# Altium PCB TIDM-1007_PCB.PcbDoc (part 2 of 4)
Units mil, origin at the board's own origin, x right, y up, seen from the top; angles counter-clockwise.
Board outline 9645.67 x 3346.46 mil, 6 copper layers (Top Layer, Signal Layer 1, Signal Layer 2, Signal Layer 3, Signal Layer 4, Bottom Layer), stack 60.2 mil thick; 189 components, 109 nets, 620 pads, 278 vias.
Unrouted connection lines stored in the file: 5.
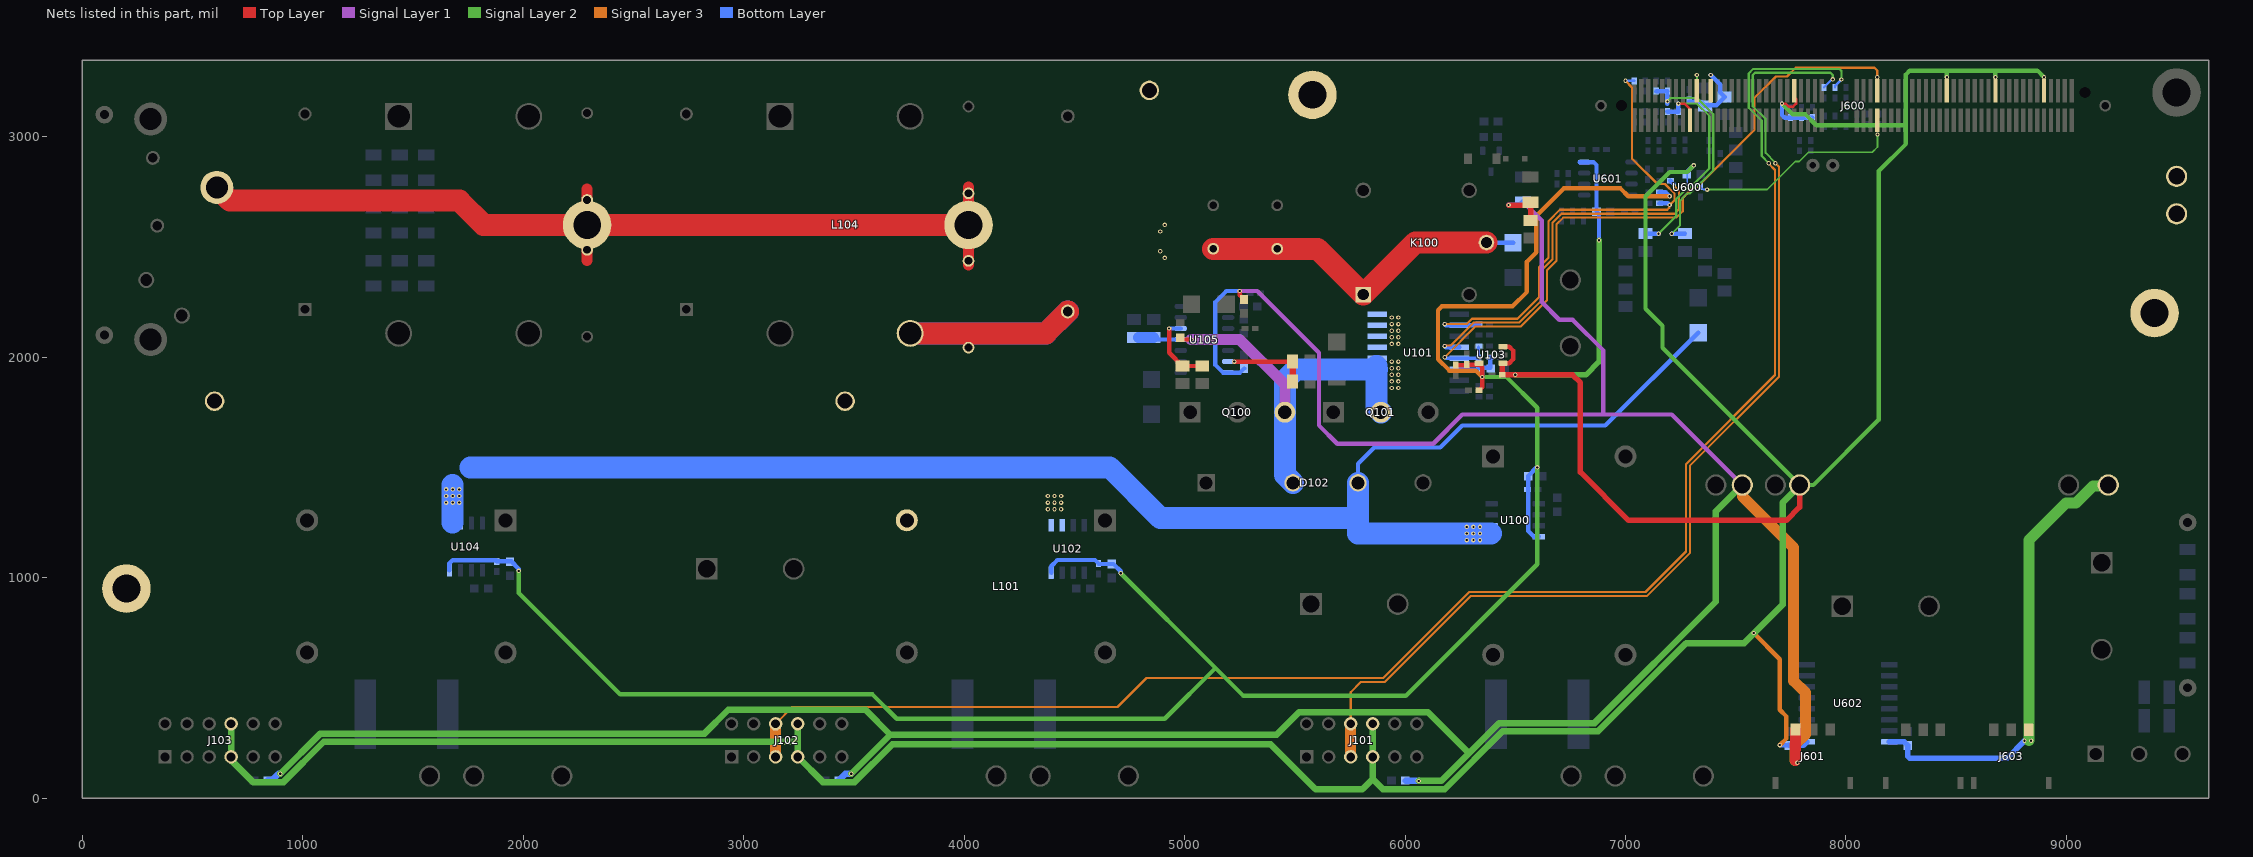
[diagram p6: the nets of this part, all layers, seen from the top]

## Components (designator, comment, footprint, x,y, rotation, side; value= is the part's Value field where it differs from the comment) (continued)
TP600 "Suggest using a net name here" Mill-Max_0312-0-15-15-34-27-10-0 6750,2350 r0 top
TP601 "Suggest using a net name here" Mill-Max_0312-0-15-15-34-27-10-0 9500,2820 r90 top
TP602 "Suggest using a net name here" Mill-Max_0312-0-15-15-34-27-10-0 6750,2050 r90 top
TP603 "Suggest using a net name here" Mill-Max_0312-0-15-15-34-27-10-0 9500,2650 r90 top
TP604 "Suggest using a net name here" Mill-Max_0312-0-15-15-34-27-10-0 7530,1420 r90 top
TP605 "Suggest using a net name here" Mill-Max_0312-0-15-15-34-27-10-0 9190,1420 r90 top
TP606 "Suggest using a net name here" Mill-Max_0312-0-15-15-34-27-10-0 7410,1420 r90 top
TP607 "Suggest using a net name here" Mill-Max_0312-0-15-15-34-27-10-0 9010,1420 r90 top
TP608 "Suggest using a net name here" Mill-Max_0312-0-15-15-34-27-10-0 7790,1420 r90 top
TP609 "Suggest using a net name here" Mill-Max_0312-0-15-15-34-27-10-0 7680,1420 r90 top
U100 "ACS722LLCTR-10AB-T" SOIC-8 6500,1260 r0 bottom
U101 "ACS716KLATR-12CB-NL-T" SOIC-16 6060,2020 r0 bottom
U102 "ACS722LLCTR-10AB-T" SOIC-8 4470,1130 r270 bottom
U103 "TLV71333PQDBVRQ1" DBV0005A_N 6390,2010 r180 top
U104 "ACS722LLCTR-10AB-T" SOIC-8 1740,1140.32 r270 bottom
U105 "UCC27714D" D0014A_N 5090,2080 r180 bottom
U600 "SN74LVC1G3157DRYR" DRY0006A 7280,2770 r90 bottom
U601 "OPA2376AIDG4" D0008A_N 6920,2810 r180 bottom
U602 "ISO7831DWR" DW0016B_N 8010,430 r0 bottom

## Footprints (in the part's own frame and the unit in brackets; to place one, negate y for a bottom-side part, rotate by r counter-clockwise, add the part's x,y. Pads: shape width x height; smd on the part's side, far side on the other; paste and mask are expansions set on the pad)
5S [mm] "TH, 4-Leads, Body 4.6x30mm"
  rect 2x2 hole 1.5: 1(-12.5,0)
  round 2 hole 1.5: 2(-2.5,0) 3(5,0) 4(12.5,0)
  silkscreen extent -15,-1.55 15,3.05, body extent -15,-1.55 15,3.05, height 24
0402 [mm] "0402 from SM-752 data"
  rect 0.8x0.6 smd: 1(-0.6,0) 2(0.6,0)
  silkscreen extent -1.22,-0.52 1.22,0.52, body extent -0.55,-0.3 0.55,0.3, height 0.6
0603 [mm] "0603 from SM-752 data"
  rect 1x0.95 smd: 1(-0.8,0) 2(0.8,0)
  silkscreen extent -1.52,-0.69 1.52,0.69, body extent -0.87,-0.47 0.87,0.47, height 1
0805_HV [mil] "0805 with 30mil clearance between pads"
  rect 50x63 smd: 1(-40,0) 2(40,0)
  silkscreen extent -74,-40 74,40, body extent -43,-29 43,29, height 57
1206 [mm] "1206 from SM-752 data"
  rect 1.3x1.85 smd: 1(-1.45,0) 2(1.45,0)
  silkscreen extent -2.4,-1.21 2.4,1.21, body extent -1.7,-0.9 1.7,0.9, height 1.35
1210_220 [mm] "1210"
  rect 1.3x2.7 smd: 1(-1.45,0) 2(1.45,0)
  silkscreen extent -2.32,-1.57 2.32,1.57, body extent -1.7,-1.35 1.7,1.35, height 2.2
B32923_15mm [mm] "Epcos film capacitors, 22.5mm spacing"
  rect 1.5x1.5 hole 1: 1(-11.25,0)
  round 1.5 hole 1: 2(11.25,0)
  silkscreen extent -13.25,-3 13.25,3, body extent -13.25,-3 13.25,3, height 15
B58031I_1084x785x450 [mm] "SMD, 2-Leads, Body 6.84x7.85mm"
  rect 2.5x8 smd: 1(-4.75,0) 2(4.75,0)
  silkscreen extent -3.2,-3.92 3.2,3.93, body extent -5.67,-4.17 5.67,4.18, height 4.5
controlCARD-120HSEC [mm] "Pads are not numbered according to Samtec datasheet."
  rect 0.5x2.724 smd: 1(-23.357,-1.678) 2(-23.357,1.722) 3(-22.557,-1.678) 4(-22.557,1.722) 5(-21.757,-1.678) 6(-21.757,1.722) 7(-20.957,-1.678) 8(-20.957,1.722) 9(-20.157,-1.678) 10(-20.157,1.722) 11(-19.357,-1.678) 12(-19.357,1.722) 13(-18.557,-1.678) 14(-18.557,1.722) 15(-17.757,-1.678) 16(-17.757,1.722) 17(-16.957,-1.678) 18(-16.957,1.722) 19(-16.157,-1.678) 20(-16.157,1.722) 21(-15.357,-1.678) 22(-15.357,1.722) 23(-14.557,-1.678) 24(-14.557,1.722) 25(-13.757,-1.678) 26(-13.757,1.722) 27(-12.957,-1.678) 28(-12.957,1.722) 29(-12.157,-1.678) 30(-12.157,1.722) 31(-11.357,-1.678) 32(-11.357,1.722) 33(-10.557,-1.678) 34(-10.557,1.722) 35(-9.757,-1.678) 36(-9.757,1.722) 37(-8.957,-1.678) 38(-8.957,1.722) 39(-8.157,-1.678) 40(-8.157,1.722) 41(-7.357,-1.678) 42(-7.357,1.722) 43(-6.557,-1.678) 44(-6.557,1.722) 45(-5.757,-1.678) 46(-5.757,1.722) 47(-4.957,-1.678) 48(-4.957,1.722) 49(-4.157,-1.678) 50(-4.157,1.722) 51(-3.357,-1.678) 52(-3.357,1.722) 53(-2.557,-1.678) 54(-2.557,1.722) 55(-1.757,-1.678) 56(-1.757,1.722) 57(2.243,-1.678) 58(2.243,1.722) 59(3.043,-1.678) 60(3.043,1.722) 61(3.843,-1.678) 62(3.843,1.722) 63(4.643,-1.678) 64(4.643,1.722) 65(5.443,-1.678) 66(5.443,1.722) 67(6.243,-1.678) 68(6.243,1.722) 69(7.043,-1.678) 70(7.043,1.722) 71(7.843,-1.678) 72(7.843,1.722) 73(8.643,-1.678) 74(8.643,1.722) 75(9.443,-1.678) 76(9.443,1.722) 77(10.243,-1.678) 78(10.243,1.722) 79(11.043,-1.678) 80(11.043,1.722) 81(11.843,-1.678) 82(11.843,1.722) 83(12.643,-1.678) 84(12.643,1.722) 85(13.443,-1.678) 86(13.443,1.722) 87(14.243,-1.678) 88(14.243,1.722) 89(15.043,-1.678) 90(15.043,1.722) 91(15.843,-1.678) 92(15.843,1.722) 93(16.643,-1.678) 94(16.643,1.722) 95(17.443,-1.678) 96(17.443,1.722) 97(18.243,-1.678) 98(18.243,1.722) 99(19.043,-1.678) 100(19.043,1.722) 101(19.843,-1.678) 102(19.843,1.722) 103(20.643,-1.678) 104(20.643,1.722) 105(21.443,-1.678) 106(21.443,1.722) 107(22.243,-1.678) 108(22.243,1.722) 109(23.043,-1.678) 110(23.043,1.722) 111(23.843,-1.678) 112(23.843,1.722) 113(24.643,-1.678) 114(24.643,1.722) 115(25.443,-1.678) 116(25.443,1.722) 117(26.243,-1.678) 118(26.243,1.722) 119(27.043,-1.678) 120(27.043,1.722)
  round 0.025 hole 1.27 unplated mask+0.876: 181(-24.857,0.022) 182(28.543,1.522)
  round 1.348 hole 0.84: 185(-27.207,0.022) 186(30.893,0.022)
  silkscreen extent -32.11,-3.86 35.8,3.9, body extent -31.75,-3.48 35.3,3.52, height 12.35
D0008A_N [mm] "SOIC, 8-Leads, Body 4.9x3.9mm, Pitch 1.27mm, IPC Medium Density"
  oval 1.45x0.6 smd: 1(-2.725,1.905) 2(-2.725,0.635) 3(-2.725,-0.635) 4(-2.725,-1.905) 5(2.725,-1.905) 6(2.725,-0.635) 7(2.725,0.635) 8(2.725,1.905)
  silkscreen extent -3.3,-2.5 0.9,2.5, body extent -3,-2.45 3,2.45, height 1.63
D0014A_N [mm] "SOIC, 14-Leads, Body 8.7x3.9mm, Pitch 1.27mm, IPC Medium Density"
  oval 1.45x0.6 smd: 1(-2.725,3.81) 2(-2.725,2.54) 3(-2.725,1.27) 4(-2.725,0) 5(-2.725,-1.27) 6(-2.725,-2.54) 7(-2.725,-3.81) 8(2.725,-3.81) 9(2.725,-2.54) 10(2.725,-1.27) 11(2.725,0) 12(2.725,1.27) 13(2.725,2.54) 14(2.725,3.81)
  silkscreen extent -3.3,-4.4 0.9,4.4, body extent -3.02,-4.32 3.02,4.32, height 1.6
DBV0005A_N [mm] "SOT23, 5-Leads, Body 2.9x1.6mm, Pitch 0.95mm, Lead Span 2.8mm, IPC Medium Density"
  rrect17% 1x0.6 smd: 1(-1.375,0.95) 2(-1.375,0) 3(-1.375,-0.95) 4(1.375,-0.95) 5(1.375,0.95)
  silkscreen extent -1.63,-1.55 0.38,1.55, body extent -1.42,-1.46 1.42,1.46, height 1.09
DE1_600x400x900 [mm] "TH, 2-Leads, Dia 6mm, Lead Spacing 10mm"
  round 1.35 hole 0.9: 1(-5,0) 2(5,0)
  silkscreen extent -3,-1.65 3,1.65, body extent -5.35,-2 5.35,2, height 9
DRY0006A [mm] "PSON, 6-Leads, Body 1x1.45mm, Pitch 0.5mm, TI Recommended"
  rect 0.35x0.2 smd: 1(-0.275,0.5)
  rect 0.3x0.2 smd: 2(-0.3,0) 3(-0.3,-0.5) 4(0.3,-0.5) 5(0.3,0) 6(0.3,0.5)
  silkscreen extent -0.5,-0.85 0.2,0.85, body extent -0.53,-0.75 0.53,0.75, height 0.61
DW0016B_N [mm] "SOIC, 16-Leads, Body 10.5x7.6mm, Pitch 1.27mm, IPC Medium Density"
  rrect17% 1.9x0.6 smd: 1(-4.75,4.445) 2(-4.75,3.175) 3(-4.75,1.905) 4(-4.75,0.635) 5(-4.75,-0.635) 6(-4.75,-1.905) 7(-4.75,-3.175) 8(-4.75,-4.445) 9(4.75,-4.445) 10(4.75,-3.175) 11(4.75,-1.905) 12(4.75,-0.635) 13(4.75,0.635) 14(4.75,1.905) 15(4.75,3.175) 16(4.75,4.445)
  silkscreen extent -5.6,-5.25 3.4,5.25, body extent -5.17,-5.15 5.17,5.15, height 2.59
FUSE_0325_Verical [mm] "TH, 2-Leads, Dia 6.985mm, Verical, Pin Spacing 5.8025mm"
  round 1.85 hole 1.35: 1(0,0) 2(-5.802,0)
  silkscreen extent -3.64,-3.64 3.64,3.64, body extent -6.34,-3.64 3.64,3.64, height 37.62
Hirose_DF59-3S-2V_51 [mm] "Receptacle, 2mm, 3x1, SMT"
  rect 1.1x1.4 smd: 1(-2,7.9) 2(0,7.9) 3(2,7.9)
  rect 0.65x1.4 smd: MP1(-4.31,1.75) MP2(4.31,1.75)
  silkscreen extent -4.6,2.75 4.6,8.25, body extent -4.6,0.35 4.6,8.3, height 2.3
IND_7840-09-0014 [mil] "NOVA MAGNETICS"
  rrect4% 100x100 hole 63.5: 1(-300,450)
  round 100 hole 63.5: 2(300,450) 3(300,-450) 4(-300,-450)
  silkscreen extent -500,-690 435,690, body extent -433,-690 433,690, height 1305
Keystone5000 [mil] "For Keystone 500x miniature loop terminals"
  round 80 hole 40: 1(0,0)
  silkscreen extent -58,-58 58,58, body extent -49,-49 49,49, height 182
Keystone5001 [mil] "For Keystone 500x miniature loop terminals"
  round 80 hole 40: 1(0,0)
  silkscreen extent -58,-58 58,58, body extent -49,-49 49,49, height 182
KMW_2200x4000 [mm] "TH, 2-Leads, Dia 22mm, Pin Spacing 10mm"
  rect 2.5x2.5 hole 2: 1(-5,0)
  round 2.5 hole 2: 2(5,0)
  silkscreen extent -11.5,-11.5 11.5,11.5, body extent -11.5,-11.49 11.51,11.5, height 42.51
Mill-Max_0312-0-15-15-34-27-10-0 [mm] "Pin Receptacle, .032-.046\" .075\" Dia, Gold, TH"
  round 2.45 hole 1.905: 1(0,0)
  silkscreen extent -1.52,-1.52 1.52,1.52, body extent -1.15,-1.15 1.16,1.15, height 0.46
Molex_0448120024 [mm] "Receptacle, 2.54mm, 6x1, TH"
  round 1.55 hole 1.02: 1(-6.35,-1.905) 2(-3.81,-1.905) 2(-3.81,1.905) 3(-1.27,-1.905) 3(-1.27,1.905) 4(1.27,-1.905) 4(1.27,1.905) 5(3.81,-1.905) 5(3.81,1.905) 6(6.35,-1.905) 6(6.35,1.905)
  rect 1.55x1.55 hole 1.02: 1(-6.35,1.905)
  silkscreen extent -8.2,-4.09 8.08,3.4, body extent -7.92,-4.09 8.08,3.4, height 4.5
RELAY_875 [mm] "TH, 5-Leads, Body 21x16mm"
  rect 1.8x1.8 hole 1.3: 1(-6,7.1)
  round 1.8 hole 1.3: 2(6,7.1) 3(0,-7.1) 4(-6,-5.1) 5(6,-5.1)
  silkscreen extent -8.5,-9.15 8,11.85, body extent -8,-9.15 8,11.85, height 20.6
SMA [mm] "Molded Diode, 2-Leads, Body 4.3x2.6mm, IPC Medium Density, based on OnSemi component dimensions and land pattern"
  rect 2x2 smd: 1(-2,0) 2(2,0)
  silkscreen extent -3.66,-1.57 2.79,1.57, body extent -2.6,-1.3 2.6,1.3, height 2.42
SOD-123 [mm] "On Semi recommended land pattern"
  rect 0.915x1.22 smd: 1(-1.637,0) 2(1.637,0)
  silkscreen extent -2.74,-1.17 2.03,1.17, body extent -1.93,-0.9 1.93,0.9, height 1.35
sod-323 [mm] "NXP recommended land pattern"
  rect 0.6x0.6 smd paste-0.05: 1(-1.1,0) 2(1.1,0)
  silkscreen extent -2.06,-0.86 1.53,0.86, body extent -1.3,-0.67 1.3,0.68, height 1.1
SOIC-8 [mm] "duplicate of SO-8.  SOIC, 8-Leads, Body 5.0x4.0mm (max), Pitch 1.27mm, IPC Medium Density"
  rrect17% 1.45x0.6 smd: 1(-2.725,1.905) 2(-2.725,0.635) 3(-2.725,-0.635) 4(-2.725,-1.905) 5(2.725,-1.905) 6(2.725,-0.635) 7(2.725,0.635) 8(2.725,1.905)
  silkscreen extent -3.5,-2.5 0.9,2.5, body extent -3,-2.45 3,2.45, height 1.63
SOIC-16 [mm] "SOIC, 16-Leads, Body 10.3x7.5mm, Pitch 1.27mm"
  rect 2.25x0.65 smd: 1(-4.75,4.445) 2(-4.75,3.175) 3(-4.75,1.905) 4(-4.75,0.635) 5(-4.75,-0.635) 6(-4.75,-1.905) 7(-4.75,-3.175) 8(-4.75,-4.445) 9(4.75,-4.445) 10(4.75,-3.175) 11(4.75,-1.905) 12(4.75,-0.635) 13(4.75,0.635) 14(4.75,1.905) 15(4.75,3.175) 16(4.75,4.445)
  silkscreen extent -4.87,-5.25 3.8,5.44, body extent -3.8,-5.25 3.8,5.25, height 2.65
SOT-23 [mm] "SOT23, 3-Leads, Body 2.9x1.3mm, Pitch 0.95mm, Lead Span 2.5mm, IPC Medium Density"
  rrect50% 1x0.6 smd: 1(-1.2,0.95) 2(-1.2,-0.95) 3(1.2,0)
  silkscreen extent -1.62,-1.5 0.7,1.5, body extent -1.16,-1.45 1.21,1.45, height 1
TDK_B751 [mm] "TH, 2-Leads, Dia 12.5mm, Pin Spacing 5mm"
  round 1.35 hole 0.85: 1(0,2.5) 2(0,-2.5)
  silkscreen extent -3.5,-6.25 3.5,6.25, body extent -3.48,-6.2 3.48,6.25, height 16.49
TE_282856-3 [mm] "Receptacle, 3x1, 5mm, R/A, TH"
  rect 1.9x1.9 hole 1.4: 1(-5,0)
  round 1.9 hole 1.4: 2(0,0) 3(5,0)
  silkscreen extent -8,-5 8,5, body extent -7.5,-5 8,5, height 19
TO-247 [mil] "Standard TO-247"
  rect 95x95 hole 62: 1(-215,0)
  round 95 / inner round 74.8 / far side round 96 hole 62: 2(0,0) 3(215,0)
  silkscreen extent -318,-124 318,81, body extent -318,-124 318,81, height 1007
VAR_S10K275E2 [mm] "EPCOS"
  round 1.6 hole 1.1: 1(-3.75,1.1) 2(3.75,-1.1)
  silkscreen extent -6,-2.7 6,2.7, body extent -5.98,-2.7 5.98,2.7, height 14.99
WCAP-FTX2_2600x1500x2500 [mm] "TH, 2-Leads, Body 26x15mm, Pin Spacing 22.5mm"
  round 1.6 hole 1.1: 1(-11.25,0) 2(11.25,0)
  silkscreen extent -13,-7.5 13,7.5, body extent -13,-7.5 13,7.5, height 25
WE-CMBNC_XL [mm] "TH, 4-Leads, Body 37x23mm"
  rect 3.1x3.1 hole 2.6: 1(-7.5,12.5)
  round 3.1 hole 2.6: 2(-7.5,-12.5) 3(7.5,-12.5) 4(7.5,12.5)
  silkscreen extent -10.3,-16.17 10.3,16.17, body extent -10.3,-16.17 10.3,16.17, height 30.09

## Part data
C100 C101 C102 C103: "CAP, AL, 220 µF, 450 V, +/- 20%, TH", Cap_Case=22x40mm, Manufacturer=Chemi-Con, Supplier Part Number 1=EKMW451VSN221MP40S-ND, Tolerance_%=20, Value1=Unknown, Value2=450V, ValueDisplayed=220µF
C104 C105: "CAP, CERM, 0.047 µF, 630 V, +/- 10%, X7R, 1210", Cap_Case=1210, Manufacturer=MuRata, Supplier Part Number 1=490-3516-1-ND, TempCo=X7R, Tolerance_%=10, Value1=Unknown, Value2=630V, ValueDisplayed=0.047µF
C106 C117 C126: "CAP, CERM, 1 µF, 500 V, +/- 20%, B58031, AEC-Q200 Grade 0, 6.84x7.85mm", Cap_Case=10.84x7.85x4.5mm, Manufacturer=TDK, Supplier Part Number 1=495-6707-ND, TempCo=B58031, Tolerance_%=20, Value1=Unknown, Value2=500V, ValueDisplayed=1µF
C107 C108 C112 C113: library part CMP-0077651-2, "CAP CER 220PF 250V RAD", Cap_Case=6x4x9mm, Manufacturer=MuRata, PartNumber=DE1B3RA221KN4AN01F, TempCo=B, Tolerance_%=10%, ValueDisplayed=220pF
C109 C110: "CAP, Film, 0.33 µF, 630 V,+/- 20%, TH", Manufacturer=TDK, Supplier Part Number 1=495-4205-ND, Tolerance_%=20, Value2=630V, ValueDisplayed=0.33µF
C111 C118 C121 C124 C130 C131 C133: "CAP, CERM, 0.1uF, 6.3V, +/-10%, X7R, 0402", Cap_Case=0402, Manufacturer=MuRata, Supplier Part Number 1=GRM155R70J104KA01D-ND, TempCo=X7R, Tolerance_%=10, Value1=Unknown, Value2=6.3V, ValueDisplayed=0.1uF
C114: "CAP, Film, 2.2 µF, 275 V, +/- 10%, TH", Cap_Case=26x15x25mm, Manufacturer="Wurth Elektronik", Supplier Part Number 1=732-5914-ND, Tolerance_%=10, Value1=Unknown, Value2=275V, ValueDisplayed=2.2µF
C115 C119 C123 C132: "CAP, CERM, 1uF, 6.3V, +/-10%, X5R, 0603", Cap_Case=0603, Manufacturer=MuRata, Supplier Part Number 1=81-GRM185R60J105KE26, TempCo=X5R, Tolerance_%=10, Value1=Unknown, Value2=6.3V, ValueDisplayed=1µF
C116 C125 C134 C139 C140: "CAP, CERM, 1000 pF, 50 V, +/- 10%, C0G/NP0, 0603", Cap_Case=0603, Manufacturer=AVX, Supplier Part Number 1=478-3718-1-ND, TempCo=C0G/NP0, Tolerance_%=10, Value1="0.048 ohm", Value2=50V, ValueDisplayed=1000pF
C120: "CAP, CERM, 1000pF, 16V, +/-10%, X7R, 0603", Cap_Case=0603, Manufacturer=MuRata, Supplier Part Number 1=GRM188R71C102KA01D-ND, TempCo=X7R, Tolerance_%=10, Value1=Unknown, Value2=16V, ValueDisplayed=1000pF
C122: "CAP, CERM, 1uF, 16V, +/-10%, X5R, 0805", Cap_Case=0805, Manufacturer=AVX, Supplier Part Number 1=478-1411-1-ND, TempCo=X5R, Tolerance_%=10, Value1="0.012 ohm", Value2=16V, ValueDisplayed=1µF
C127 C128: "CAP, CERM, 1000pF, 6.3V, +/-10%, X5R, 0402", Cap_Case=0402, Manufacturer=MuRata, Supplier Part Number 1=GRM155R60J102KA01D-ND, TempCo=X5R, Tolerance_%=10, Value1=Unknown, Value2=6.3V, ValueDisplayed=1000pF
C129: "CAP, CERM, 0.022uF, 6.3V, +/-10%, X7R, 0402", Cap_Case=0402, Manufacturer=MuRata, Supplier Part Number 1=GRM155R70J223KA01D-ND, TempCo=X7R, Tolerance_%=10, Value1=Unknown, Value2=6.3V, ValueDisplayed=0.022uF
C135 C137: "CAP, CERM, 10uF, 16V, +/-20%, X5R, 0805", Cap_Case=0805, Manufacturer=AVX, Supplier Part Number 1=1582704, TempCo=X5R, Tolerance_%=20, Value1=Unknown, Value2=16V, ValueDisplayed=10uF
C136: "CAP, CERM, 0.01uF, 50V, +/-10%, X7R, 0603", Cap_Case=0603, Manufacturer=Kemet, Supplier Part Number 1=399-5346-1-ND, TempCo=X7R, Tolerance_%=10, Value1=Unknown, Value2=50V, ValueDisplayed=0.01µF
C138 C600 C605 C615 C616: "CAP, CERM, 1uF, 25V, +/-10%, X7R, 0603", Cap_Case=0603, Manufacturer=TDK, Supplier Part Number 1=445-5956-1-ND, TempCo=X7R, Tolerance_%=10, Value1=Unknown, Value2=25V, ValueDisplayed=1uF
C601 C604 C607 C611 C612 C613 C617: "CAP, CERM, 0.01uF, 6.3V, +/-10%, X7R, 0402", Cap_Case=0402, Manufacturer=MuRata, Supplier Part Number 1=GRM155R70J103KA01D-ND, TempCo=X7R, Tolerance_%=10, Value1=Unknown, Value2=6.3V, ValueDisplayed=0.01uF
C602: "CAP, CERM, 0.1 µF, 16 V, +/- 10%, X7R, 0402", Cap_Case=0402, Manufacturer=MuRata, Supplier Part Number 1=490-4759-2-ND, TempCo=X7R, Tolerance_%=10, Value1=Unknown, Value2=16V, ValueDisplayed=0.1µF
C603: "CAP, CERM, 0.1uF, 6.3V, +/-10%, X5R, 0402", Cap_Case=0402, Manufacturer=MuRata, Supplier Part Number 1=GRM155R60J104KA01D-ND, TempCo=X5R, Tolerance_%=10, Value1=Unknown, Value2=6.3V, ValueDisplayed=0.1µF
C606 C609 C610: "CAP, CERM, 470 pF, 50 V,+/- 10%, X7R, AEC-Q200 Grade 1, 0402", Cap_Case=0402, Manufacturer=TDK, Supplier Part Number 1=445-6888-1-ND, TempCo=X7R, Tolerance_%=10, Value1="4.96489 ohm", Value2=50V, ValueDisplayed=470pF
C608: "CAP, CERM, 0.047 µF, 10 V, +/- 10%, X5R, 0402", Cap_Case=0402, Manufacturer=TDK, Supplier Part Number 1=445-4980-1-ND, TempCo=X5R, Tolerance_%=10, Value1=Unknown, Value2=10V, ValueDisplayed=0.047µF
C614: "CAP, CERM, 47 pF, 25 V, +/- 5%, C0G/NP0, 0402", Cap_Case=0402, Manufacturer=MuRata, Supplier Part Number 1=81-GRM1555C1E470JA1D, TempCo=C0G/NP0, Tolerance_%=5, Value1=Unknown, Value2=25V, ValueDisplayed=47pF
D100 D104: "Diode, Fast Rectifier, 800 V, 1 A, SMA", Manufacturer="Diodes Inc.", Supplier Part Number 1=US1K-FDICT-ND, Value1=1A, Value2=1.7V
D101 D103: "Diode, Schottky, 30 V, 1 A, SMA", Manufacturer=STMicroelectronics, Supplier Part Number 1=497-3755-2-ND, Value1=1A, Value2=0.46V
D102: "Diode, Switching-Bridge, 600 V, 3.5 A, TH", Manufacturer=Shindengen, Supplier Part Number 1=627-D25XB60-7000, Value1=3.5A, Value2=1.05V
D105: "Diode, Zener, 12 V, 500 mW, SOD-123", Manufacturer="ON Semiconductor", Power_W=0.5, Supplier Part Number 1=MMSZ4699T1GOSCT-ND, Value1=0.5W
D106: "Diode, Ultrafast, 100 V, 0.25 A, SOD-323", Manufacturer="NXP Semiconductor", Supplier Part Number 1=568-5003-1-ND, Value1=0.25A, Value2=1.4V
D107: "Diode, Ultrafast, 600V, 1A, SMA", Manufacturer="ON Semiconductor", Supplier Part Number 1=MURA160T3GOSCT-ND, Value1=1A, Value2=1.05V
F100: "Fuse, 20 A, 250 VAC, 60 VDC, TH", Irating_A=20A, Manufacturer=Littelfuse, Supplier Part Number 1=F3336-ND
J101 J102 J103: "Receptacle, 2.54mm, 6x1, Gold, TH", Color=Black, Manufacturer=Molex, Supplier Part Number 1=WM18605-ND
J104: "Receptacle, 3x1, 5mm, R/A, TH", Color=Green, Current_A=24, Manufacturer="TE Connectivity", Supplier Part Number 1=A98356-ND, Voltage_V=300
J600: library part controlCARD-120HSEC, "C2000 controlCARD-120HSEC connector, SMT", Manufacturer=Samtec
J601 J602 J603: "Receptacle, 2mm, 3x1, Gold, Natural, SMT", Color=Natural, Current_A=3, Manufacturer="Hirose Electric Co. Ltd.", Supplier Part Number 1=H11965CT-ND, Voltage_V=230
K100: "Relay, SPDT ( 1 Form C), 16A, 12 VDC, TH", Coil Current="30 mA", Coil Power="360 mW", Coil Resistance="400 ohms", Coil Voltage="12 VDC", Contact Rating=16A, Manufacturer="SONG CHUAN", Supplier Part Number 1=893-875B1CCFS12VDC, Turn Off Voltage (Min)="0.6 VDC", Turn On Voltage (Max)="9 VDC"
L100 L101 L102: library part CMP-0074586-1, "Inductor, Toroid, 0.065 ohm, TH", Manufacturer="GCI Technologies", Value1="0.065 ohm", Value2=A
L103: library part 7448052303, "COMMON MODE CHOKE", Manufacturer="Wurth Elektronik", ValueDisplayed=7mH
L104: library part 7448052303, "CMC 12MH 10A 2LN TH", Manufacturer="Wurth Elektronik", Supplier Part Number 1=732-5597-ND, ValueDisplayed=12mH
Q100 Q101: library part STY105NM50N, "MOSFET N-CH 650V 138A MAX247", Alternate Manufacturer=None, Manufacturer=STMicroelectronics, Supplier Part Number 1=497-13638-5-ND, Value1="? ohm", Value2="326 nC"
Q102: "MOSFET, N-CH, 60V, 0.26A, SOT-23", Alternate Manufacturer=None, Manufacturer="ON Semiconductor", Supplier Part Number 1=2N7002ET1GOSCT-ND, Value1="3 ohm", Value2="0.81 nC"
R100 R101 R102 R119 R121 R123 R602 R605 R607: "RES, 348k ohm, 0.1%, 0.125W, 0805", Manufacturer="Yageo America", Power_W=0.125, TempCo="25 ppm/C", Tolerance_%=0.1, Value1=0.1%, Value2=0.125W, Value_Code=348k
R103 R114: "RES, 10.0, 1%, 0.125 W, 0805", Manufacturer=Vishay-Dale, Power_W=0.125, Supplier Part Number 1=541-10.0CCT-ND, TempCo="100 ppm/C", Tolerance_%=1, Value1=1%, Value2=0.125W, Value_Code=10R0, ValueDisplayed=10.0
R104 R115: "RES, 4.99 k, 1%, 0.125 W, 0805", Manufacturer=Panasonic, Power_W=0.125, Supplier Part Number 1=P4.99KCCT-ND, TempCo="100 ppm/C", Tolerance_%=1, Value1=1%, Value2=0.125W, Value_Code=4k99, ValueDisplayed=4.99k
R105 R106 R107 R108 R109 R110 R111 R112 R113 R129 R130 R131: "RES, 330 k, 5%, 0.25 W, 1206", Manufacturer=Vishay-Dale, Power_W=0.25, Supplier Part Number 1=541-330KECT-ND, TempCo="200 ppm/C", Tolerance_%=5, Value1=5%, Value2=0.25W, Value_Code=330k
R116: "RES, 10.0k ohm, 1%, 0.063W, 0402", Manufacturer=Vishay-Dale, Power_W=0.063, Supplier Part Number 1=541-10.0KLCT-ND, TempCo="100 ppm/C", Tolerance_%=1, Value1=1%, Value2=0.063W, Value_Code=10k0
R117: "RES, 12.7k ohm, 1%, 0.063W, 0402", Manufacturer=Vishay-Dale, Power_W=0.063, Supplier Part Number 1=541-12.7KLCT-ND, TempCo="100 ppm/C", Tolerance_%=1, Value1=1%, Value2=0.063W, Value_Code=12k7
R118 R120: "RES, 150, 5%, 0.25 W, 1206", Manufacturer=Vishay-Dale, Power_W=0.25, Supplier Part Number 1=541-150ECT-ND, TempCo="200 ppm/C", Tolerance_%=5, Value1=5%, Value2=0.25W, Value_Code=150R, ValueDisplayed=150
R122: "RES, 10.0k ohm, 1%, 0.1W, 0603", Manufacturer="Yageo America", Power_W=0.1, Supplier Part Number 1=311-10.0KHRCT-ND, TempCo="200 ppm/C", Tolerance_%=1, Value1=1%, Value2=0.1W, Value_Code=10k0
R124: "RES, 5.49k ohm, 1%, 0.063W, 0402", Manufacturer=Vishay-Dale, Power_W=0.063, Supplier Part Number 1=541-5.49KLCT-ND, TempCo="100 ppm/C", Tolerance_%=1, Value1=1%, Value2=0.063W, Value_Code=5k49
R125: "RES, 330k ohm, 5%, 0.063W, 0402", Manufacturer=Vishay-Dale, Power_W=0.063, Supplier Part Number 1=541-330KJCT-ND, TempCo="200 ppm/C", Tolerance_%=5, Value1=5%, Value2=0.063W, Value_Code=330k
R126: "RES, 200 ohm, 1%, 0.1W, 0603", Manufacturer=Vishay-Dale, Power_W=0.1, Supplier Part Number 1=541-200HCT-ND, TempCo="100 ppm/C", Tolerance_%=1, Value1=1%, Value2=0.1W, Value_Code=200R
R127 R128: "RES, 1.0k ohm, 5%, 0.063W, 0402", Manufacturer=Vishay-Dale, Power_W=0.063, Supplier Part Number 1=541-1.0KJCT-ND, TempCo="200 ppm/C", Tolerance_%=5, Value1=5%, Value2=0.063W, Value_Code=1k00
R132 R133 R134: "RES, 0, 5%, 0.1 W, 0603", Manufacturer=Vishay-Dale, Power_W=0.1, Supplier Part Number 1=541-0.0GCT-ND, TempCo="200 ppm/C", Tolerance_%=5, Value1=5%, Value2=0.1W, Value_Code=0000, ValueDisplayed=0
R600 R603 R608 R630: "RES, 1.40k ohm, 1%, 0.063W, 0402", Manufacturer=Vishay-Dale, Power_W=0.063, Supplier Part Number 1=541-1.40KLCT-ND, TempCo="100 ppm/C", Tolerance_%=1, Value1=1%, Value2=0.063W, Value_Code=1k40
R601 R606: "RES, 3.57 k, 1%, 0.063 W, 0402", Manufacturer=Vishay-Dale, Power_W=0.063, Supplier Part Number 1=541-3.57KLCT-ND, TempCo="100 ppm/C", Tolerance_%=1, Value1=1%, Value2=0.063W, Value_Code=3k57, ValueDisplayed=3.57k
R604: "RES, 10k ohm, 5%, 0.063W, 0402", Manufacturer=Vishay-Dale, Power_W=0.063, Supplier Part Number 1=541-10KJCT-ND, TempCo="200 ppm/C", Tolerance_%=5, Value1=5%, Value2=0.063W, Value_Code=10k0
R609: "RES, 7.50 k, 1%, 0.125 W, 0805", Manufacturer=Vishay-Dale, Power_W=0.125, Supplier Part Number 1=541-7.50KCCT-ND, TempCo="100 ppm/C", Tolerance_%=1, Value1=1%, Value2=0.125W, Value_Code=7k50, ValueDisplayed=7.50k
R610 R619: "RES, 1.00 k, 1%, 0.063 W, 0402", Manufacturer=Vishay-Dale, Power_W=0.063, Supplier Part Number 1=541-1.00KLCT-ND, TempCo="100 ppm/C", Tolerance_%=1, Value1=1%, Value2=0.063W, Value_Code=1k00, ValueDisplayed=1.00k
R611: "RES, 33.2, 1%, 0.063 W, 0402", Manufacturer=Vishay-Dale, Power_W=0.063, Supplier Part Number 1=541-33.2LCT-ND, TempCo="100 ppm/C", Tolerance_%=1, Value1=1%, Value2=0.063W, Value_Code=33R2, ValueDisplayed=33.2
R612 R615 R622 R623 R627 R628 R629: "RES, 10.0 k, 1%, 0.063 W, 0402", Manufacturer=Vishay-Dale, Power_W=0.063, Supplier Part Number 1=541-10.0KLCT-ND, TempCo="100 ppm/C", Tolerance_%=1, Value1=1%, Value2=0.063W, Value_Code=10k0, ValueDisplayed=10.0k
R613: "RES, 4.87 k, 0.1%, 0.062 W, AEC-Q200 Grade 0, 0402", Manufacturer=Panasonic, Power_W=0.062, Supplier Part Number 1=P4.87KDCCT-ND, TempCo="25 ppm/C", Tolerance_%=0.1, Value1=0.1%, Value2=0.062W, Value_Code=4k87, ValueDisplayed=4.87k
R614 R621 R625 R626: "RES, 0, 5%, 0.063 W, 0402", Manufacturer=Vishay-Dale, Power_W=0.063, Supplier Part Number 1=541-0.0JCT-ND, TempCo="200 ppm/C", Tolerance_%=5, Value1=5%, Value2=0.063W, Value_Code=0000, ValueDisplayed=0
R616 R617: "RES, 7.50 k, 1%, 0.063 W, 0402", Manufacturer=Vishay-Dale, Power_W=0.063, Supplier Part Number 1=541-7.50KLCT-ND, TempCo="100 ppm/C", Tolerance_%=1, Value1=1%, Value2=0.063W, Value_Code=7k50, ValueDisplayed=7.50k
R618 R620 R624: "RES, 4.99 k, 1%, 0.063 W, 0402", Manufacturer=Vishay-Dale, Power_W=0.063, Supplier Part Number 1=541-4.99KLCT-ND, TempCo="100 ppm/C", Tolerance_%=1, Value1=1%, Value2=0.063W, Value_Code=4k99, ValueDisplayed=4.99k
R631 R632 R633: "RES, 9.31 k, 1%, 0.063 W, 0402", Manufacturer=Vishay-Dale, Power_W=0.063, Supplier Part Number 1=541-9.31KLCT-ND, TempCo="100 ppm/C", Tolerance_%=1, Value1=1%, Value2=0.063W, Value_Code=9k31, ValueDisplayed=9.31k
RT100 RT101: "Thermistor NTC, 50 ohm, 25%, D12.5xH16.5mm", Manufacturer=TDK, Supplier Part Number 1=495-3880-ND, Tolerance_%=25
RV100: "Varistor 275V RMS 10MM Radial, TH", Manufacturer="EPCOS Inc", Supplier Part Number 1=495-1433-ND
TP100 TP101: library part 5000, "Test Point, Miniature, Red, TH", Manufacturer=Keystone, Supplier Part Number 1=36-5000-ND
TP102 TP103: library part 5001, "Test Point, Miniature, Black, TH", Manufacturer=Keystone, Supplier Part Number 1=36-5001-ND
TP104 TP105 TP106 TP107 TP108 TP109 TP110 TP111 TP112 TP600 TP601 TP602 TP603 TP604 TP605 TP606 TP607 TP608 TP609: library part 0312-0-15-15-34-27-10-0, "Pin Receptacle, .032-.046\" .075\" Dia, Gold, TH", Manufacturer=Mill-Max, Supplier Part Number 1=0312-015153427100-ND
U100 U102 U104: "High Accuracy, Galvanically Isolated Current Sensor IC, SOIC-8", Manufacturer="Allegro Microsystems Inc", Supplier Part Number 1=620-1635-1-ND
U101: "SENSOR CURRENT HALL 12.5A AC/DC", Manufacturer="Allegro Microsystems Inc", Supplier Part Number 1=620-1526-1-ND
U103: "Capacitor-Free, 150-mA, Low-Dropout Regulator with Foldback Current Limit for Portable Devices, DBV0005A", Alternate Manufacturer="Texas Instruments"
U105: "High-Speed,4A, 600V High-side Low-side Gate Driver Device, D0014A", Alternate Manufacturer="Texas Instruments"
U600: "SINGLE-POLE DOUBLE-THROW ANALOG SWITCH, DRY0006A", Alternate Manufacturer="Texas Instruments"
U601: "Precision, Low Noise, Low Quiescent Current Operational Amplifier, 2 to 5.5 V, -40 to 125 degC, 8-pin SOIC (D0008A), Green (RoHS & no Sb/Br)", Alternate Manufacturer="Texas Instruments", Alternate PartNumber=Equivalent, Supplier Part Number 1=OPA2376AIDG4-ND, Total Supply Voltage(Max)(+5V is 5, +/-5V is 10)=5.5, Total Supply Voltage(Min)(+5V is 5, +/-5V is 10)=2
U602: "High-Performance, 8000 VPK Reinforced Triple Digital Isolator, DW0016B", Alternate Manufacturer="Texas Instruments", Alternate PartNumber=ISO7831DW

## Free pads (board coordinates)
  round 150 hole 100: 0(310,2080) 0(310,3080) 0(610,2770)
  round 220 hole 126: 2(200,950) 2(2290,2600) 2(4020,2600) 2(5580,3190) 2(9400,2200) 2(9500,3200)
  round 60 hole 30: 3(7940,2870) 4(7850,2870)
  round 88.58 hole 68.11: 5(600,1800) 5(3460,1800) 5(4840,3210)

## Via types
v1: diameter 20, hole 10, Top Layer to Bottom Layer, 278 vias

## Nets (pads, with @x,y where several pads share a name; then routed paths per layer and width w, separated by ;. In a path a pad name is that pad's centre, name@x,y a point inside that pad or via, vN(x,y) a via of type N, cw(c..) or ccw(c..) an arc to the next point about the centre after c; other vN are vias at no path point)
3V3: C111.1 C115.1 C118.1 C119.1 C121.1 C123.1 C130.1 C131.1 C132.1 R116.2 R117.2 R125.1 R612.2 U100.8 U101.14 U102.8 U103.5 U104.8 | length 10543.1
  Top Layer w20: R117.2@6230,1963.62 C131.1@6277.24,1963.62 ; C131.1@6280,1966.38 6337.91,1966.38 6350,1954.29 v1(6350,1910) 6350,1864.38 R116.2@6335.62,1850
  Signal Layer 2 w20: v1(1980,1030.32) 1980,930 2440,470 3584.25,470 3694.25,360 4910,360 5140,590 ; v1(4710,1020) 5140,590 ; v1(6350,1910) 6460,1910 6600,1770 v1(6600,1500) 6600,1060 6003.15,463.15 5266.85,463.15 5140,590
  Signal Layer 3 w20: v1(6350,1910) 6320.87,1939.13 6201.45,1939.13 6149.63,1990.95 6149.63,2212.58 6167.42,2230.37 6487.42,2230.37 6552.81,2295.77 6552.81,2432.21 6595.63,2475.02 6595.63,2640.77 6720.23,2765.37 6977.58,2765.37 7012.96,2730 v1(7200,2730)
  Bottom Layer w14: U101.14@6247.01,1945 6331.38,1945 R125.1@6336.38,1950
  Bottom Layer w20: U104.8@1665,1033.03 1665,1063.9 1680.55,1079.45 1880,1079.45 C130.1@1880,1073.94 1945.12,1073.94 1980,1039.06 v1(1980,1030.32) ; U102.8@4395,1022.72 4395,1051.69 4423.31,1080 4593.62,1080 C121.1@4610,1063.62 4612.13,1061.5 C123.1@4670,1061.5 4677.25,1061.5 4710,1028.74 v1(4710,1020) ; R125.1@6337.48,1951.1 6386.38,1951.1 C118.1@6386.38,2000 ; v1(6350,1910) 6350,1940 ; v1(6600,1500) 6597.83,1500 6558.5,1460.67 C115.1@6558.5,1460 6558.5,1211.52 6585.02,1185 U100.8@6607.28,1185 ; R612.2@7153.62,2748.19 7181.81,2748.19 v1(7200,2730)
5VP: C133.1 C600.2 C605.2 C615.2 J101.4 J102.4 J103.4 J600.48 J600.84 J600.98 J600.112 R618.2 R620.2 R624.2 TP608.1 U103.1 U103.3 U600.5 U601.8 U602.1 | length 18887.4
  Top Layer w12: v1(7710,3150) 7726.13,3150 7740,3136.13 7759.89,3136.13 7773.87,3150.11 7773.87,3169.89 J600.48@7764.84,3178.92 ; J600.48@7764.84,3178.92 7761.88,3181.88 7761.88,3204.83 J600.48@7764.84,3207.8 J600.48@7764.84,3178.92
  Top Layer w20: U103.1@6444.13,1972.6 6472.6,1972.6 6490,1990 6490,2030 6472.6,2047.4 U103.3@6444.13,2047.4
  Top Layer w25: U103.1@6441.12,1969.59 C133.1@6441.12,1920 v1(6500,1920) 6760,1920 6795.64,1884.36 6795.64,1478.35 7013.99,1260 7730,1260 7790,1320 TP608.1@7790,1420
  Signal Layer 2 w20: v1(7310,2870) 7280,2840 7200.54,2840 7090.75,2730.21 7090.75,2219.25 7167.87,2142.13 7167.87,2042.13 TP608.1@7790,1420 7852.37,1420 8149.25,1716.88 8149.25,2844.28 8272.13,2967.16 8272.13,3050 ; v1(7710,3150) 7758.86,3101.14 7816.5,3101.14 7865.36,3052.28 8269.84,3052.28 8272.13,3050 ; v1(8458,3270) 8458,3298 ; v1(8678,3270) 8678,3298 ; v1(8898.5,3270) 8868.5,3300 8290,3300 8272.13,3282.13 8272.13,3050
  Signal Layer 2 w25: v1(6500,1920) 6820,1920 6880,1980 v1(6880,2530)
  Signal Layer 2 w29.53: J103.4@675,337 J103.4@675,187 675,172.11 774.51,72.6 913.13,72.6 1095.47,254.94 3240.06,254.94 ; J102.4@3245,337 J102.4@3245,187 3359.4,72.6 3503.13,72.6 3674.68,244.15 5390,244.15 5594.15,40 5806.89,40 5853.45,86.55 ; J101.4@5853.45,337 J101.4@5853.45,187 5853.45,86.55 ; TP608.1@7790,1420 7790,1417.36 7712.64,1340 7712.64,876.48 7538.08,701.92 7274.82,701.92 6875.49,302.6 6442.6,302.6 6180,40 5900,40 5853.45,86.55
  Signal Layer 3 w20: v1(7581.46,748.54) 7700,630 7700,400 7730,370 7730,270 v1(7700,240)
  Bottom Layer w7.87: U600.5@7280,2781.81 C600.2@7280,2828.5
  Bottom Layer w20: U601.8@6792.72,2885 U601.8@6812.72,2885 6855,2885 6868.5,2871.5 C605.2@6868.5,2660 6880,2648.5 v1(6880,2530) ; C600.2@7278.5,2838.5 v1(7310,2870) ; v1(7700,240) C615.2@7738.5,240 ; v1(7710,3150) 7710,3098.46 7722.08,3086.38 R624.2@7747.97,3086.38 R620.2@7797.97,3086.38 R618.2@7847.97,3086.38
  Bottom Layer w25: C615.2@7740,238.5 7806.5,238.5 U602.1@7822.99,255
5VS: C616.2 J603.3 TP605.1 U602.16 | length 2107
  Signal Layer 2 w50: v1@8830,260 8830,1170 8998.9,1338.9 9043.59,1338.9 9091.1,1386.41 9120,1415.3 9185.3,1415.3 TP605.1@9190,1420
  Bottom Layer w25: U602.16@8197.01,255 8263.5,255 C616.2@8278.5,240 ; C616.2@8280,238.5 8280,190 8290,180 8730,180 v1(8810,260) v1(8840,260)
12VP: C122.2 C136.1 J601.1 R118.2 R120.2 R126.2 R132.2 R133.2 R134.2 TP604.1 U105.7 | length 14946.7
  Top Layer w20: v1(5250,2300) 5250,2281.5 R126.2@5270,2261.5
  Top Layer w25: v1(6470,2690) 6556.77,2690 R118.2@6569.69,2702.91 C122.2@6569.69,2620.31
  Top Layer w50: 7771.26,171.26 J601.1@7771.26,311.02
  Signal Layer 1 w20: v1(5250,2300) 5330,2300 5609.63,2020.37 5609.63,1690.37 5692.5,1607.5 6127.5,1607.5 6260,1740 6900,1740 ; v1(6470,2690) 6550,2690 6620,2620 6620,2250 6700,2170 6760,2170 6900,2030 6900,1740 ; TP604.1@7530,1420 7210,1740 6900,1740
  Signal Layer 2 w29.53: v1(897.64,110) 1079.98,292.34 2822.34,292.34 2930,400 3552.65,400 3665.15,287.51 ; v1(3487.64,110) 3665.15,287.51 ; v1(6062.6,77.4) 6164.51,77.4 6290,202.89 ; TP604.1@7530,1420 7410,1300 7410,890 6860,340 6427.11,340 6290,202.89 ; 3665.15,287.51 5417.36,287.51 5520,390.15 6102.74,390.15 6290,202.89
  Signal Layer 3 w50: TP604.1@7530,1420 7530,1368.15 7762.13,1136.03 7762.13,532.13 7815.75,478.5 7815.75,288.15 7770,242.4 7770,170
  Bottom Layer w20: v1(5250,2300) 5189.72,2300 5140,2250.28 5140,1964.36 5174.36,1930 U105.7@5197.28,1930 5251.5,1930 C136.1@5270,1948.5
  Bottom Layer w25: v1(6470,2690) 6521.34,2690 R120.2@6534.25,2702.91
  Bottom Layer w29.53: R134.2@841.5,80 859.98,80 889.98,110 v1(897.64,110) ; R133.2@3431.5,80 3461.5,110 v1(3487.64,110) ; R132.2@6004.09,77.4 v1(6062.6,77.4)
  other v1: 7780,160
12VS: TP601.1
+BRDG_N: R103.2 R104.2 U105.12 | length 337.6
  Top Layer w20: v1(4930,2130) 4930,2020 R103.2@4990,1960 R104.2@5080,1960
  Bottom Layer w20: v1(4930,2130) U105.12@4982.72,2130
+BRDG_P: R114.2 R115.2 U105.6 | length 354.7
  Top Layer w20: v1(5225.33,1980) R114.2@5490,1980
  Top Layer w29.53: R115.2@5490,1890 R114.2@5490,1980
-BRDG_N: C135.2 C137.2 C138.1 D102.2 Q100.3 Q101.2 U101.1 U101.2 U101.3 U101.4 U105.11 | length 2053.5
  Top Layer w20: C138.1@4988.5,2080 v1(5030,2080)
  Signal Layer 1 w50: v1(5030,2080) 5250,2080 5455,1875 Q100.3@5455,1750
  Bottom Layer w20: C137.2@4780,2080 C137.2@4790,2080 ; C135.2@4870,2080 U105.11@4982.72,2080 v1(5030,2080)
  Bottom Layer w50: C137.2@4790,2090 C135.2@4860,2090
  Bottom Layer w100: D102.2@5491.57,1430 5455,1466.57 Q100.3@5455,1750 5455,1895 5505,1945 U101.3@5870,1945 ; 5870,1960 U101.3@5870,1945 ; U101.3@5872.99,1945 U101.3@5870,1945 ; Q101.2@5890,1750 5870,1770 U101.3@5870,1945
  other v1: 5940,1860 5970,1860 5940,1890 5970,1890 5940,1920 5970,1920 5940,1950 5970,1950 5940,1980 5970,1980
AC_CUR_FAULT: C129.2 J600.64 R125.2 U101.13 | length 3044.2
  Signal Layer 3 w10: v1(6180,2000) 6318.88,2138.88 6525.32,2138.88 6644.31,2257.87 6644.31,2394.31 6687.13,2437.13 6687.13,2602.87 6717.13,2632.87 7230.75,2632.87 7260,2662.13 7260,2722.35 7307.65,2770 7323.63,2770 7585.63,3032 7585.63,3176.74 7682.39,3273.5 7732.6,3273.5 7771.97,3312.87 8129.88,3312.87 8142.5,3300.26 v1(8142.5,3270)
  Bottom Layer w14: v1(6180,2000) 6185,1995 U101.13@6247.01,1995 6332.33,1995 C129.2@6332.33,2045.95
AC_CUR_SENSE: R610.1 U101.12 | length 1711.3
  Signal Layer 3 w10: v1(6180,2050) 6182.44,2052.44 6207.16,2052.44 6311.47,2156.75 6517.91,2156.75 6626.44,2265.28 6626.44,2401.71 6669.25,2444.53 6669.25,2610.28 6709.72,2650.75 7223.34,2650.75 7242.13,2669.53 7242.13,2754.69 v1(7220,2776.81)
  Bottom Layer w20: v1(6180,2050) 6185,2045 U101.12@6247.01,2045 ; R610.1@7203.62,2800 7220,2783.62 v1(7220,2776.81)
AC_CUR_VREF: C128.1 R604.2 R614.2 U101.10 | length 2363.2
  Signal Layer 3 w10: v1(6180,2150) 6279.44,2150 6304.07,2174.63 6510.51,2174.63 6608.56,2272.68 6608.56,2409.12 6651.38,2451.93 6651.38,2617.68 6702.32,2668.62 7190,2668.62 7200,2678.62 v1(7200,2690) 7222.87,2712.87 7222.87,2741.59 7179.46,2785 7145,2785 7030,2900 7030,3223.62 v1(7000,3253.62)
  Bottom Layer w10: v1(7000,3253.62) R604.2@7040,3253.62
  Bottom Layer w20: v1(6180,2150) 6185,2145 U101.10@6247.01,2145 6315,2145 6320,2150 C128.1@6336.38,2150 ; R614.2@7153.62,2698.19 7191.81,2698.19 v1(7200,2690)
AC_L: C108.1 C114.1 D100.2 D102.3 L101.4 L104.3 U100.1 U100.2 U102.1 U102.2 U104.1 U104.2 | length 8512.4
  Top Layer w100: L104.3@3755.28,2107.87 4370.79,2107.87 C114.1@4470,2207.09
  Bottom Layer w20: D102.3@5786.85,1430 5786.85,1516.85 5860,1590 6160,1590 6260,1690 6908.74,1690 D100.2@7330,2111.26
  Bottom Layer w100: 1680,1250 v1(1680,1340) v1(1680,1370) v1(1680,1400) 1680,1420 ; 1760,1500 4660,1500 4890,1270 5756.85,1270 5786.85,1300 ; L104.3@3755.28,2107.87 4270,2107.87 4370.79,2107.87 C114.1@4470,2207.09 ; 5786.85,1200 5786.85,1300 ; D102.3@5786.85,1430 5786.85,1300 ; 5800,1200 6390,1200
  other v1: 6280,1170 6310,1170 6340,1170 6280,1200 6310,1200 6340,1200 6280,1230 6310,1230 6340,1230 4380,1310 4410,1310 4440,1310 1650,1340 1710,1340 4380,1340 4410,1340 4440,1340 1650,1370 1710,1370 4380,1370 4410,1370 4440,1370 1650,1400 1710,1400
AC_N: D104.2 K100.1 K100.3 RT100.2 RT101.2 U101.5 U101.6 U101.7 U101.8 | length 1542.7
  Top Layer w100: RT101.2@5130,2491.57 RT100.2@5420,2491.57 5602.68,2491.57 K100.1@5810.47,2283.78 6046.69,2520 K100.3@6369.53,2520
  Bottom Layer w20: K100.3@6370.79,2518.74 D104.2@6490,2518.74
  other v1: 5940,2060 5970,2060 5940,2090 5970,2090 5940,2120 5970,2120 5940,2150 5970,2150 5940,2180 5970,2180 4910,2450 4890,2480 4890,2570 4910,2600
ACL_SENSE: C610.1 J600.20 R100.1 R617.2 | length 1126.2
  Signal Layer 2 w10: v1(7190,3160) 7205.64,3175.64 7324,3175.64 ; v1(7210,2560) 7247.87,2597.87 7247.87,2710 7267.13,2729.25 7267.13,2729.47 7280.53,2742.87 7292.4,2742.87 7397.87,2848.35 7397.87,3101.76 7324,3175.64 ; v1(7324,3280) 7324,3175.64
  Bottom Layer w20: R617.2@7140,3206.38 C610.1@7190,3206.38 ; 7190,3150 v1(7190,3160) 7190,3190.31 ; v1(7210,2560) R100.1@7270,2560
ACN_SENSE: C609.1 J600.17 R123.1 R616.2 | length 1059.9
  Top Layer w12: v1(7240,3150) 7267.48,3150 7292.4,3125.08 J600.17@7292.4,3073.94
  Signal Layer 2 w10: v1(7150,2560) 7230,2640 7230,2717.4 7249.25,2736.66 7249.25,2736.88 7273.12,2760.75 7285,2760.75 7380,2855.75 7380,3094.36 7324.36,3150 v1(7240,3150)
  Bottom Layer w20: R123.1@7090,2560 v1(7150,2560) ; C609.1@7190,3113.62 R616.2@7240,3113.62 v1(7240,3150)
ADC_A0: C606.1 J600.24 R607.1 R609.2 | length 313.5
  Bottom Layer w20: C606.1@7288.5,3158.5 7341.5,3158.5 R609.2@7360,3140 7360,3142.87 7412.87,3142.87 R607.1@7450,3180 7430,3200 7430,3237 v1(7387,3280)
EARTH: C107.2 C108.2 C112.1 C113.2 pad.0@610,2770 pad.2@200,950 pad.2@2290,2600 pad.2@4020,2600 pad.2@5580,3190 pad.2@9400,2200 pad.5 TP603.1 | length 4159.9
  Top Layer w50: 2290,2437.64 pad.2@2290,2600 2290,2762.36 ; C108.2@4020,2417.64 pad.2@4020,2600 4020,2772.36
  Top Layer w100: pad.0@610,2770 670,2710 1710,2710 1820,2600 pad.2@2290,2600 pad.2@4020,2600
G_AC_I: C602.1 J600.63 U600.6 | length 979.3
  Signal Layer 2 w7.87: 7380,2760 7642.09,2760 7769.5,2887.41 7787.41,2887.41 7830,2930 8120,2930 8143,2953 v1(8143,3010)
  Bottom Layer w7.87: U600.6@7299.69,2781.81 7331.81,2781.81 C602.1@7340,2773.62 7353.62,2760 v1(7370,2760)
GAN_F1: J101.3 R621.2 | length 4924.7
  Signal Layer 2 w10: v1(7680,2880) 7680,2882.35 7635.75,2926.6 7635.75,3079.9 7577.13,3138.53 7577.13,3279.46 7587.4,3289.74 7930,3289.74 7940,3279.74 v1(7940,3260)
  Signal Layer 3 w10: J101.3@5753.45,337 5753.45,480.46 5800,527.01 5909.23,527.01 6299.23,917.01 7098.12,917.01 7292.13,1111.02 7292.13,1507.4 7696.34,1911.62 7696.34,2863.66 v1(7680,2880)
  Signal Layer 3 w50: J101.3@5753.45,187 J101.3@5753.45,337
  Bottom Layer w10: R621.2@7900,3223.62 7936.38,3260 v1(7940,3260)
GAN_F2: J102.3 R625.2 | length 7507.6
  Signal Layer 2 w10: v1(7650,2880) 7617.87,2912.13 7617.87,3072.5 7559.25,3131.12 7559.25,3286.87 7580,3307.61 7970,3307.61 7979.46,3298.15 v1(7979.46,3259.37)
  Signal Layer 3 w10: J102.3@3145,337 3220.76,412.76 4695.28,412.76 4827.4,544.88 5901.83,544.88 6291.83,934.88 7090.71,934.88 7274.25,1118.42 7274.25,1295.19 7274.25,1514.81 7678.46,1919.02 7678.46,2849.19 7650,2877.65 v1(7650,2880)
  Signal Layer 3 w50: J102.3@3145,187 J102.3@3145,337
  Bottom Layer w10: R625.2@7950,3223.62 7950,3229.91 v1(7979.46,3259.37)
